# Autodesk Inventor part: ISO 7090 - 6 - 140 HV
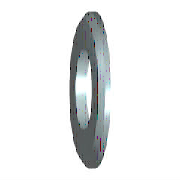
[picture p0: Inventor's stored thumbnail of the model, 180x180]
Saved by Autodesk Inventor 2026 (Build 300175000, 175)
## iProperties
IsCustomPart: 1
Created: 2022-02
Part Number: ISO 7090 - 6 - 140 HV
Material: Steel, Mild
Description: Plain washers, chamfered - Normal series - Product grade A
Document SubType Name: Modeling
Standard: ISO 7090
Designer: Lars Bertram Pedersen
Standard Revision: Second edition 2000-06-01
Standards Organization: ISO
Language: en-US
Size Designation: 6 - 140 HV
Categories: <MemberInstance><Categories><Category DisplayName="Fasteners" InternalName="e4da775c-781d-43d5-af7c-5136215cf5a6" Mnemonic="FSTN"><Category DisplayName="Washers
Density: 7.85 g/cm^3
Appearance: Semi-Polished
Mass: 0.925957 g
Surface Area: 2.35844 cm^2
Volume: 0.117956 cm^3
Stock Number: Lager
Author: Lars Bertram Pedersen
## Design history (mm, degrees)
workaxis "Work Axis1"
workplane "Work Plane1"
body "Solid1"
sketch "Sketch"
  geometry: C1 r 6 at (0, 0); C2 r 3.2 at (0, 0); 1 further point
  constraints: 2 centre point, 2 coincident
  dimensions: "d0" = 6.4 diameter of C2 (= SD1); "d1" = 12 diameter of C1 (= SD2)
extrude "Body" new body sketch "Sketch" distance "d2" = 1.6 (= SD); taper "d3" = 0 deg
chamfer "Chamfer" distance "d4" = 0.8 (= PHH); stored, may be unused: angle "d5" = 45 deg, second distance "d8" = 0.8 (= PHH)
other parameters: "SD1" = 6.4 [user parameter; used in 1 equation term], "SD2" = 12 [user parameter; used in 1 equation term], "SD" = 1.6 [user parameter; used in 1 equation term], "PHH" = 0.8 [user parameter; used in 2 equation terms], "FAWI" = 45 deg [user parameter], "d6" = 0, "d7" = 0, "d9" = 0, "d10" = 0, "NND" = 6 [user parameter]
